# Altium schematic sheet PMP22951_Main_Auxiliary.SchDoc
size 431 x 279 mm; Date: Not shown in title block; ApprovedBy: Not shown in title block; CheckedBy: Not shown in title block; Author: Not shown in title block; CompanyName: Not shown in title block; Engineer: Not shown in title block; Organization: Not shown in title block; Address1: Not shown in title block; Address2: Not shown in title block; Address3: Not shown in title block; Address4: Not shown in title block; DocumentNumber: 3; Revision: Use project parameter SCH_Rev; SheetNumber: 3; SheetTotal: 3; PageSetup: Record=PageOptions¦CenterHorizontal=True¦CenterVertical=True¦PrintScale=1.00¦XCorrection=1.00¦YCorrection=1.00¦PrintKind=0¦BorderSize=5000000¦LeftOffset=0¦BottomOffset=0¦Orientation=2¦PaperLength=1000¦PaperWidth=1000¦Scale=100¦PaperSource=15¦PrintQuality=600¦MediaType=1¦DitherType=10¦PaperKind=Letter¦PrintScaleMode=1
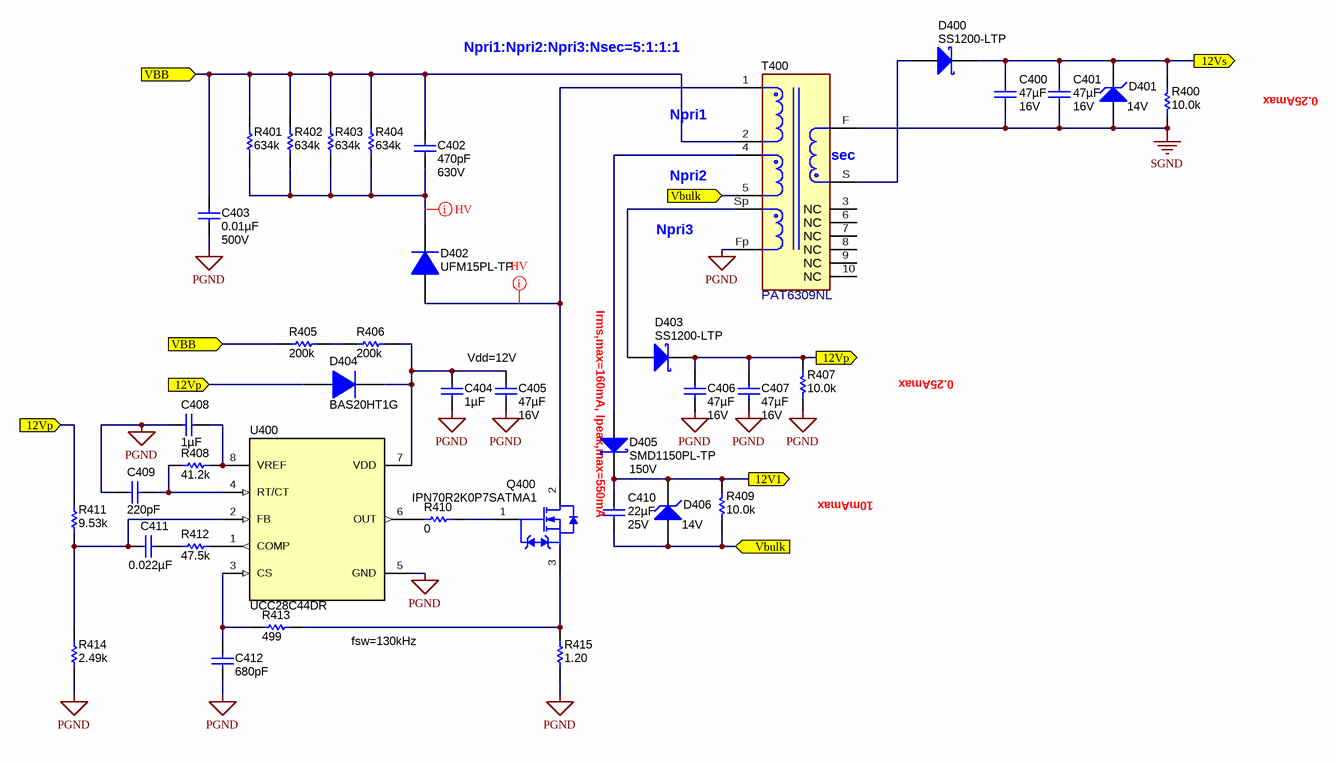
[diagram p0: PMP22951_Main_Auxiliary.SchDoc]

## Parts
C400  ValueDisplayed: 47µF  Value2: 16V  [1210_270]  (hidden comment: GRM32ER61C476KE15L)
C401  ValueDisplayed: 47µF  Value2: 16V  [1210_270]  (hidden comment: GRM32ER61C476KE15L)
C402  ValueDisplayed: 470pF  Value2: 630V  [1206]  (hidden comment: C3216C0G2J471J085AA)
C403  ValueDisplayed: 0.01µF  Value2: 500V  [1206]  (hidden comment: VJ1206Y103KXEAT5Z)
C404  ValueDisplayed: 1µF  [0805_HV]  (hidden comment: CL21B105KBFNNNE)
C405  ValueDisplayed: 47µF  Value2: 16V  [1210_270]  (hidden comment: GRM32ER61C476KE15L)
C406  ValueDisplayed: 47µF  Value2: 16V  [1210_270]  (hidden comment: GRM32ER61C476KE15L)
C407  ValueDisplayed: 47µF  Value2: 16V  [1210_270]  (hidden comment: GRM32ER61C476KE15L)
C408  ValueDisplayed: 1µF  [1206]  (hidden comment: C1206C105K3RACTU)
C409  ValueDisplayed: 220pF  [0603]  (hidden comment: 06031C221KAT2A)
C410  ValueDisplayed: 22µF  Value2: 25V  [0805_HV]  (hidden comment: GRM21BR61E226ME44L)
C411  ValueDisplayed: 0.022µF  [0402]  (hidden comment: GRM155R61C223KA01D)
C412  ValueDisplayed: 680pF  [0402]  (hidden comment: GRM1555C1H681JA01D)
D400  SS1200-LTP  [SMA]
D401  value 14V  [SOD-123]  (hidden comment: MMSZ4701T1G)
D402  UFM15PL-TP  [SOD-123FL]
D403  SS1200-LTP  [SMA]
D404  BAS20HT1G  [sod-323]
D405  SMD1150PL-TP  value 150V  [SOD-123]
D406  value 14V  [SOD-123]  (hidden comment: MMSZ4701T1G)
Q400  IPN70R2K0P7SATMA1  [PG-SOT223]
R400  ValueDisplayed: 10.0k  [0603]  (hidden comment: CRCW060310K0FKEA)
R401  ValueDisplayed: 634k  [1206]  (hidden comment: CRCW1206634KFKEA)
R402  ValueDisplayed: 634k  [1206]  (hidden comment: CRCW1206634KFKEA)
R403  ValueDisplayed: 634k  [1206]  (hidden comment: CRCW1206634KFKEA)
R404  ValueDisplayed: 634k  [1206]  (hidden comment: CRCW1206634KFKEA)
R405  ValueDisplayed: 200k  [1206]  (hidden comment: CRCW1206200KFKEA)
R406  ValueDisplayed: 200k  [1206]  (hidden comment: CRCW1206200KFKEA)
R407  ValueDisplayed: 10.0k  [0603]  (hidden comment: CRCW060310K0FKEA)
R408  ValueDisplayed: 41.2k  [0603]  (hidden comment: CRCW060341K2FKEA)
R409  ValueDisplayed: 10.0k  [0603]  (hidden comment: CRCW060310K0FKEA)
R410  ValueDisplayed: 0  [0603]  (hidden comment: CRCW06030000Z0EA)
R411  ValueDisplayed: 9.53k  [0402]  (hidden comment: CRCW04029K53FKED)
R412  ValueDisplayed: 47.5k  [0402]  (hidden comment: CRCW040247K5FKED)
R413  ValueDisplayed: 499  [0402]  (hidden comment: CRCW0402499RFKED)
R414  ValueDisplayed: 2.49k  [0402]  (hidden comment: CRCW04022K49FKED)
R415  ValueDisplayed: 1.20  [1206]  (hidden comment: CRCW12061R20FKEA)
T400  PAT6309NL  [FP-PAT6309NL_SMT10_14MM8_13MM5-MFG]
U400  UCC28C44DR  [D0008A_N]

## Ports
12V1 (out), 12Vp (in), 12Vp (out), 12Vs (out), VBB (in), Vbulk (in)

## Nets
PGND: C403.2 C404.2 C405.1 C406.1 C407.1 C408.2 C409.1 C412.2 R407.1 R414.1 R415.1 T400.Fp U400.5(GND)
SGND: C400.1 C401.1 D401.2(A) R400.1 T400.F
12V1: C410.1 D405.1(K) D406.1(K) R409.2 ; port 12V1
12Vp: C406.2 C407.2 D403.1(K) D404.2(A) R407.2 R411.2 ; port 12Vp
12Vs: C400.2 C401.2 D400.1(K) D401.1(K) R400.2 ; port 12Vs
VBB: C402.1 C403.1 R401.2 R402.2 R403.2 R404.2 R405.1 T400.2 ; port VBB
Vbulk: C410.2 D406.2(A) R409.1 T400.5 ; port Vbulk
NetC402_2: C402.2 D402.1(K) R401.1 R402.1 R403.1 R404.1
NetC404_1: C404.1 C405.2 D404.1(K) R406.2 U400.7(VDD)
NetC408_1: C408.1 R408.2 U400.8(VREF)
NetC409_2: C409.2 R408.1 U400.4(RT/CT)
NetC411_1: C411.1 R412.2
NetC411_2: C411.2 R411.1 R414.2 U400.2(FB)
NetC412_1: C412.1 R413.1 U400.3(CS)
NetD400_2: D400.2(A) T400.S
NetD402_2: D402.2(A) Q400.2(D) T400.1
NetD403_2: D403.2(A) T400.Sp
NetD405_2: D405.2(A) T400.4
NetQ400_1: Q400.1(G) R410.2
NetQ400_3: Q400.3(S) R413.2 R415.2
NetR405_2: R405.2 R406.1
NetR410_1: R410.1 U400.6(OUT)
NetR412_1: R412.1 U400.1(COMP)

Not connected (* = marked no-connect by the designer): T400 3(NC) 6(NC) 7(NC) 8(NC) 9(NC) 10(NC)

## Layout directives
net class HV: NetC402_2, NetD402_2

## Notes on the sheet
- Npri1:Npri2:Npri3:Nsec=5:1:1:1
- (near T400) Npri1
- (near R400) 0.25Amax
- (near T400) Npri2
- (near T400) Nsec
- (near T400) Npri3
- Vdd=12V
- (near R407) 0.25Amax
- (near C410) Irms,max=160mA, Ipeak,max=550mA
- (near R409) 10mAmax
- fsw=130kHz

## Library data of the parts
C400 C401 C405-C407 = GRM32ER61C476KE15L: CAP, CERM, 47 µF, 16 V, +/- 10%, X5R, 1210; Manufacturer: MuRata; Polarized: N; CompType: Capacitor; Value: 47uF; U/M: EA; Cap_F: 0.000047; Tolerance_%: 10; Value1: Unknown; VDC_V: 16; TaMin_C: -55; TaMax_C: 85; Cap_Case: 1210; SizeArea_mm2: 8; SizeAreaWB_mm2: 14.7; SizeX_mm: 3.2; SizeY_mm: 2.5; SizeZ_mm: 2.7; AEC Category: Q200
C402 = C3216C0G2J471J085AA: CAP, CERM, 470 pF, 630 V,+/- 5%, C0G/NP0, 1206; Manufacturer: TDK; Polarized: N; CompType: Capacitor; Value: 470pF; U/M: EA; Cap_F: 0.00000000047; Tolerance_%: 5; VDC_V: 630; TaMin_C: -55; TaMax_C: 125; SizeArea_mm2: 5.12; SizeAreaWB_mm2: 10.92; SizeX_mm: 3.2; SizeY_mm: 1.6; SizeZ_mm: 1.35; AEC Category: Q200; Green_Lifecycle: Active; Green_REACh: Passed
C403 = VJ1206Y103KXEAT5Z: CAP, CERM, 0.01 µF, 500 V,+/- 10%, X7R, 1206; Manufacturer: Vishay-Vitramon; Polarized: N; CompType: Capacitor; Value: 0.01uF; U/M: EA; Cap_F: 0.00000001; Tolerance_%: 10; VDC_V: 500; TaMin_C: -55; TaMax_C: 125; SizeArea_mm2: 5.12; SizeAreaWB_mm2: 10.92; SizeX_mm: 3.2; SizeY_mm: 1.6; SizeZ_mm: 1.35; AEC Category: Q200
C404 = CL21B105KBFNNNE: CAP, CERM, 1 µF, 50 V, +/- 10%, X7R, 0805; Manufacturer: Samsung Electro-Mechanics; Polarized: N; CompType: Capacitor; Value: 1uF; U/M: EA; Cap_F: 0.000001; Tolerance_%: 10; Value1: Unknown; VDC_V: 50; Value2: 50V; TaMin_C: -55; TaMax_C: 125; Cap_Case: 0805; AEC Category: Q200
C408 = C1206C105K3RACTU: CAP, CERM, 1 µF, 25 V, +/- 10%, X7R, 1206; Manufacturer: Kemet; Polarized: N; CompType: Capacitor; Value: 1uF; U/M: EA; Cap_F: 0.000001; Tolerance_%: 10; ESR_ohm: 0.011; Value1: 0.011 ohm; VDC_V: 25; Value2: 25V; IRMS_A: 3.55; TaMin_C: -55; TaMax_C: 125; SizeArea_mm2: 5.12; SizeAreaWB_mm2: 10.92; SizeX_mm: 3.2; SizeY_mm: 1.6; SizeZ_mm: 1.35; AEC Category: Q200
C409 = 06031C221KAT2A: CAP, CERM, 220pF, 100V, +/-10%, X7R, 0603; Manufacturer: AVX; Polarized: N; CompType: Capacitor; U/M: EA; Cap_F: 0.00000000022; Tolerance_%: 10; ESR_Ohm: 0.579; Value1: 0.579 ohm; VDC_V: 100; TaMin_C: -55; TaMax_C: 125
C410 = GRM21BR61E226ME44L: CAP, CERM, 22 µF, 25 V,+/- 20%, X5R, 0805; Manufacturer: MuRata; Polarized: N; CompType: Capacitor; Value: 22uF; U/M: EA; Cap_F: 0.000022; Tolerance_%: 20; VDC_V: 25; TaMin_C: -55; TaMax_C: 85; Cap_Case: 0805; SizeArea_mm2: 2.5; SizeAreaWB_mm2: 6.75; SizeX_mm: 2; SizeY_mm: 1.25; SizeZ_mm: 1.45; AEC Category: Q200; Green_Lifecycle: Active; Green_REACh: Passed
C411 = GRM155R61C223KA01D: CAP, CERM, 0.022 µF, 16 V, +/- 10%, X5R, 0402; Manufacturer: MuRata; Polarized: N; CompType: Capacitor; Value: 0.022uF; U/M: EA; Cap_F: 0.000000022; Tolerance_%: 10; Value1: Unknown; VDC_V: 16; Value2: 16V; TaMin_C: -55; TaMax_C: 85; SizeArea_mm2: 0.5; SizeAreaWB_mm2: 3; SizeX_mm: 1; SizeZ_mm: 0.6; AEC Category: Q200
C412 = GRM1555C1H681JA01D: CAP, CERM, 680 pF, 50 V, +/- 5%, C0G/NP0, 0402; Manufacturer: MuRata; Polarized: N; CompType: Capacitor; Value: 680pF; U/M: EA; Cap_F: 0.00000000068; Tolerance_%: 5; Value1: Unknown; VDC_V: 50; Value2: 50V; TaMin_C: -55; TaMax_C: 125; SizeArea_mm2: 0.5; SizeAreaWB_mm2: 3; SizeX_mm: 1; SizeZ_mm: 0.6; AEC Category: Q200
D400 D403 = CMP-0028981-2: Diode, Schottky, 200 V, 1 A, SMA; Manufacturer: Micro Commercial Components; TJmax_C: 150°C; SizeArea_mm2: 16.3228; Io_A: 1A; AEC Qualified: N; SizeX_mm: 5.59; SizeZ_mm: 2.87; Vf_V: 920mV; Value: 200V; AEC Category: Q101; Value2: 0.92V; SizeY_mm: 2.92; SizeAreaWB_mm2: 37.3428
D401 D406 = MMSZ4701T1G: Diode, Zener, 14 V, 500 mW, SOD-123; Manufacturer: ON Semiconductor; SymbolCreator: a0412235; U/M: EA; Power_W: 0.5; Vz_V: 14; Value1: 0.5W; RJA_CperW: 340; SizeAreaWB_mm2: 13.095; SizeArea_mm2: 6.545; SizeX_mm: 3.85; SizeY_mm: 1.7; SizeZ_mm: 1.35; AEC Category: Q101; Green_Lifecycle: Active; Green_REACh: Passed
D402 = UFM15PL-TP: Diode, Ultrafast, 600 V, 1 A, SOD-123FL; Manufacturer: Micro Commercial Components; U/M: EA; Vf_V: 1.7; Value: 600V; Value1: 1A; Value2: 1.7V; Io_A: 1; Vr_V: 600; TJmax_C: 150; SizeAreaWB_mm2: 12.19; SizeArea_mm2: 5.94; SizeX_mm: 3.6; SizeY_mm: 1.65; SizeZ_mm: 0.98; AEC Category: Q101; AEC Qualified: N; Green_Lifecycle: Not Set; Green_REACh: Incomplete
D404 = BAS316,115: DIODE SWITCH 200V 200MA SOD323; U/M: EA; Vf_V: 1.4; Value1: 0.25A; Vr_V: 100; Value2: 100V; TJmax_C: 150; Type: Ultrafast
D405 = MBR130T1G: DIODE SCHOTTKY 150V 1A SOD123FL; Manufacturer: Micro Commercial Co; U/M: EA; Vf_V: 0.47; Value2: 0.47V; Io_A: 1; Vr_V: 30; TJmax_C: 125; RJC_CperW: 108; AEC Category: Q101
Q400 = CMP-0086300-1: MOSFET, N-CH, 700 V, 30 A, PG-SOT223; Alternate Manufacturer: None; Manufacturer: Infineon Technologies; SizeArea_mm2: 45.5; IdsMax_A: 30A; AEC Qualified: N; SizeY_mm: 6.5; QgTyp_nC: 3.8; ChMode: Enhancement; VdsMax_V: 700V; AEC Category: Q101; SizeX_mm: 7; SizeZ_mm: 1.8; SizeAreaWB_mm2: 76.5; Vgs_V: 16V; Value1: ? ohm; Value: 700V; Value2: 3.8 nC
R400 R407 R409 = CRCW060310K0FKEA: RES, 10.0 k, 1%, 0.1 W, 0603; Manufacturer: Vishay-Dale; CompType: Resistor; Value: 10.0k; Res_ohm: 10000; Value_Code: 10k0; Tolerance_%: 1; Power_W: 0.1; Value2: 0.1W; VDC_V: 75; TempCo: 100 ppm/C; SizeArea_mm2: 1.28; SizeX_mm: 1.6; SizeY_mm: 0.8; EIA_Code: E96; U/M: EA; AEC Category: Q200; Green_Lifecycle: Active; Green_REACh: Passed
R401-R404 = CRCW1206634KFKEA: RES, 634 k, 1%, 0.25 W, 1206; Manufacturer: Vishay-Dale; CompType: Resistor; Value: 634k; Res_ohm: 634000; Tolerance_%: 1; Power_W: 0.25; Value2: 0.25W; VDC_V: 200; TempCo: 100 ppm/C; SizeArea_mm2: 5.12; SizeX_mm: 3.2; SizeY_mm: 1.6; SizeZ_mm: 1.35; EIA_Code: E96; U/M: EA; AEC Category: Q200
R405 R406 = CRCW1206200KFKEA: RES, 200 k, 1%, 0.25 W, 1206; Manufacturer: Vishay-Dale; CompType: Resistor; Value: 200k; Res_ohm: 200000; Tolerance_%: 1; Power_W: 0.25; Value2: 0.25W; VDC_V: 200; TempCo: 100 ppm/C; SizeArea_mm2: 5.12; SizeX_mm: 3.2; SizeY_mm: 1.6; SizeZ_mm: 1.35; EIA_Code: E96; U/M: EA; AEC Category: Q200; Green_Lifecycle: Active; Green_REACh: Passed
R408 = CRCW060341K2FKEA: RES, 41.2 k, 1%, 0.1 W, 0603; Manufacturer: Vishay-Dale; CompType: Resistor; Value: 41.2k; Res_ohm: 41200; Value_Code: 41k2; Tolerance_%: 1; Power_W: 0.1; Value2: 0.1W; VDC_V: 75; TempCo: 100 ppm/C; SizeArea_mm2: 1.28; SizeX_mm: 1.6; SizeY_mm: 0.8; EIA_Code: E96; U/M: EA; AEC Category: Q200
R410 = CRCW06030000Z0EA: RES, 0, 5%, 0.1 W, 0603; Manufacturer: Vishay-Dale; CompType: Resistor; Value: 0; Value_Code: 0000; Tolerance_%: 5; Power_W: 0.1; Value2: 0.1W; VDC_V: 75; TempCo: 200 ppm/C; EIA_Code: E24; U/M: EA; AEC Category: Q200
R411 = CRCW04029K53FKED: RES, 9.53 k, 1%, 0.063 W, 0402; Manufacturer: Vishay-Dale; CompType: Resistor; Value: 9.53k; Res_ohm: 9530; Value_Code: 9k53; Tolerance_%: 1; Power_W: 0.063; Value2: 0.063W; VDC_V: 50; TempCo: 100 ppm/C; EIA_Code: E96; U/M: EA; AEC Category: Q200
R412 = CRCW040247K5FKED: RES, 47.5 k, 1%, 0.063 W, 0402; Manufacturer: Vishay-Dale; CompType: Resistor; Value: 47.5k; Res_ohm: 47500; Value_Code: 47k5; Tolerance_%: 1; Power_W: 0.063; Value2: 0.063W; VDC_V: 50; TempCo: 100 ppm/C; SizeArea_mm2: 0.5; SizeZ_mm: 0.6; EIA_Code: E96; U/M: EA; AEC Category: Q200; Green_Lifecycle: Active; Green_REACh: Passed
R413 = CRCW0402499RFKED: RES, 499, 1%, 0.063 W, 0402; Manufacturer: Vishay-Dale; CompType: Resistor; Value: 499; Value_Code: 499R; Tolerance_%: 1; Power_W: 0.063; Value2: 0.063W; VDC_V: 50; TempCo: 100 ppm/C; EIA_Code: E96; U/M: EA; AEC Category: Q200
R414 = CRCW04022K49FKED: RES, 2.49 k, 1%, 0.063 W, 0402; Manufacturer: Vishay-Dale; CompType: Resistor; Value: 2.49k; Res_ohm: 2490; Value_Code: 2k49; Tolerance_%: 1; Power_W: 0.063; Value2: 0.063W; VDC_V: 50; TempCo: 100 ppm/C; SizeArea_mm2: 0.5; SizeZ_mm: 0.6; EIA_Code: E96; U/M: EA; AEC Category: Q200; Green_Lifecycle: Active; Green_REACh: Passed
R415 = CRCW12061R20FKEA: RES, 1.20, 1%, 0.25 W, AEC-Q200 Grade 0, 1206; Manufacturer: Vishay-Dale; CompType: Resistor; Value: 1.20; Res_ohm: 1.2; Value_Code: 1R20; Tolerance_%: 1; Power_W: 0.25; Value2: 0.25W; VDC_V: 200; TempCo: 100 ppm/C; SizeArea_mm2: 5.12; SizeX_mm: 3.2; SizeY_mm: 1.6; SizeZ_mm: 1.35; U/M: EA; AEC Category: Q200; AEC Qualified: Y; AEC Grade: 0; Green_Lifecycle: Active; Green_REACh: Passed
T400 = CMP-0091143-1: XFMR FLYBACK 550uH EF12.6 SMD; Manufacturer: Pulse Electronics; SizeZ_mm: 10mm; Frequency_Fixed: 130kHz; AEC Qualified: No; Voltage_Isolation_Vrms: 3kV; Ind_H: 495µH; Ns1toNp: 1:5
U400 = CMP-0074162-1: BiCMOS Low-Power Current Mode PWM Controller, D0008A (SOIC-8); Alternate Manufacturer: Texas Instruments; SizeAreaWB_mm2: 56.58; U/M: EA; SizeZ_mm: 1.75; SizeX_mm: 4.9; SizeY_mm: 6.2; SizeArea_mm2: 30.38; CompType: IC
